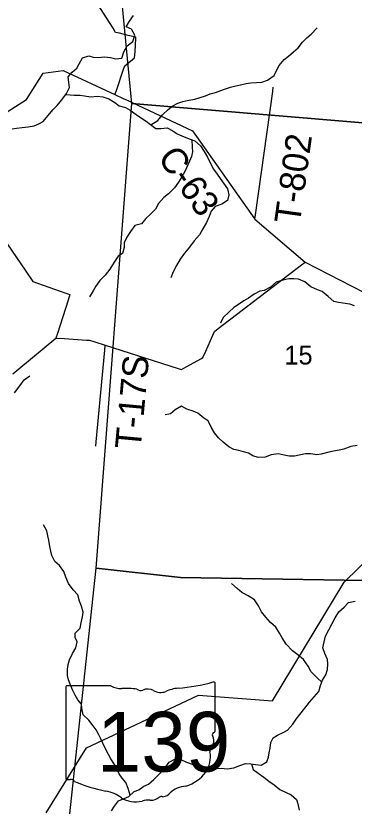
# Model space of a CAD drawing. Extents: x 1715311 to 2083412, y 146837 to 553079.
# Drawn here: x 1900643 to 1904583, y 324418 to 333622 of the extents above; entities that cross this region are included whole.
import ezdxf

# ---------------------------------------------------------------- set-up
doc = ezdxf.new("R2010")
doc.units = 0
for name, color, linetype in [('GM_X_County_Road', 7, 'Continuous'), ('GM_X_County_Road_Text', 7, 'Continuous'), ('GM_X_Minor_River', 7, 'Continuous'), ('GM_X_Section', 7, 'Continuous'), ('GM_X_Section_Text', 7, 'Continuous'), ('GM_X_State_Location', 7, 'Continuous'), ('GM_X_State_Route', 7, 'Continuous'), ('GM_X_State_Shield', 7, 'Continuous'), ('GM_X_Township_Road', 7, 'Continuous'), ('GM_X_Township_Road_Text', 7, 'Continuous'), ('GM_X_Township_ROW', 7, 'Continuous')]:
    doc.layers.add(name, color=color, linetype=linetype)

msp = doc.modelspace()

# ---------------------------------------------------------------- linework, layer by layer
at = {"layer": 'GM_X_County_Road'}
for points in [[(1895522.8, 333111.5), (1895631.1, 333150.8), (1896318.1, 332920.2), (1897109.3, 333251), (1897359.6, 333535.8), (1897940.5, 333377.3), (1899174.4, 332376.6), (1899334.6, 332039.7), (1899795.3, 331853.1), (1900055.7, 332196.1), (1900768.7, 332649.2), (1900963, 332954.1), (1901195.4, 332986.1), (1901797.2, 332704.6), (1901891.8, 332660.5)], [(1901891.8, 332660.5), (1901939.4, 332638.2)], [(1901939.4, 332638.2), (1902701.8, 332281.7), (1903427.7, 331253.6), (1904011.6, 330753.9), (1904690.6, 330402.9), (1904921, 329149.5), (1905450.8, 328846.4)]]:
    msp.add_lwpolyline(points, dxfattribs=at)
at = {"layer": 'GM_X_Minor_River'}
for points in [[(1901744.3, 333135.8), (1901808.1, 333119.5), (1901878.1, 333129.2), (1901900.3, 333201.2), (1901940.5, 333273.1), (1902004.6, 333322.9), (1902028.9, 333394.8), (1901991.2, 333465), (1901927.4, 333495.3), (1901965.6, 333561.2), (1902011.7, 333627)], [(1902216, 332353), (1902296.8, 332403.1), (1902349, 332469), (1902417.2, 332532.8), (1902469.2, 332572.6), (1902529.3, 332606.4), (1902587.3, 332624.2), (1902659.2, 332637.9), (1902727.2, 332651.6), (1902789.2, 332669.4), (1902851.2, 332691.2), (1902907.2, 332713), (1902969.2, 332730.8), (1903029.2, 332750.5), (1903085.2, 332770.3), (1903143.2, 332790.1), (1903205.2, 332805.9), (1903259.1, 332817.7), (1903323.1, 332833.5), (1903381.1, 332843.3), (1903447, 332845), (1903506.9, 332848.8), (1903574.9, 332872.5), (1903649, 332928.3), (1903683.2, 332992.2), (1903709.4, 333044.1), (1903767.6, 333114), (1903817.7, 333153.8), (1903875.8, 333201.6), (1903931.9, 333247.4), (1903980.1, 333313.3), (1904032.2, 333367.1), (1904082.3, 333409), (1904152.4, 333482.7)], [(1900598.7, 332305.6), (1900652.6, 332313.4), (1900716.6, 332321.1), (1900786.5, 332328.9), (1900856.5, 332342.6), (1900910.5, 332362.4), (1900962.5, 332392.2), (1901018.7, 332462.1), (1901074.9, 332525.9), (1901125, 332577.8), (1901177.2, 332643.6), (1901233.4, 332715.4), (1901269.6, 332787.3), (1901261.8, 332843.4), (1901252.1, 332909.5), (1901300.2, 332967.3), (1901352.3, 333011.2), (1901380.5, 333063.1), (1901420.7, 333131), (1901492.7, 333156.7), (1901544.5, 333138.5), (1901604.5, 333138.3), (1901674.4, 333146), (1901744.3, 333135.8)], [(1901227.2, 332707.5), (1901321.2, 332699.1), (1901391.1, 332696.8), (1901443, 332688.6), (1901516.9, 332678.3), (1901590.8, 332686), (1901656.7, 332677.8), (1901724.5, 332653.5), (1901796.3, 332611.2), (1901848.1, 332575), (1901919.9, 332552.7), (1901973.7, 332524.5), (1902043.4, 332472.1), (1902095.2, 332435.9), (1902159, 332395.7), (1902212.8, 332355.4), (1902274.5, 332309.1), (1902332.5, 332310.9), (1902404.4, 332316.7), (1902470.2, 332284.4), (1902522, 332248.2), (1902601.7, 332211.8), (1902673.6, 332185.5), (1902725.4, 332165.3), (1902795.1, 332109), (1902836.8, 332040.8), (1902874.5, 331976.6), (1902906.2, 331910.5), (1902945.9, 331836.2), (1902987.6, 331776), (1903023.4, 331725.9), (1903061.2, 331673.7), (1903106.9, 331607.5), (1903124.6, 331537.4), (1903108.3, 331469.4), (1903040.3, 331427.6), (1902964.3, 331399.9), (1902916.1, 331346), (1902893.9, 331284.1), (1902861.7, 331214.1), (1902821.5, 331142.2), (1902783.3, 331072.3), (1902719.1, 331000.5), (1902666.9, 330926.7), (1902608.7, 330858.9), (1902556.5, 330787), (1902512.3, 330713.1), (1902476.1, 330641.2), (1902445.9, 330571.3)], [(1902690.7, 332178.9), (1902695.2, 332091.4), (1902701, 332039.3), (1902686.8, 331985.3), (1902666.6, 331929.4), (1902630.4, 331853.5), (1902608.2, 331799.5), (1902576, 331745.6), (1902535.9, 331685.7), (1902489.7, 331617.9), (1902419.5, 331550.1), (1902365.4, 331506.3), (1902305.2, 331434.4), (1902271.1, 331370.5), (1902208.9, 331306.7), (1902156.8, 331260.9), (1902104.6, 331199), (1902026.7, 331179.3), (1901978.5, 331111.5), (1901934.3, 331043.6), (1901906.1, 330979.6), (1901903.9, 330925.6), (1901885.6, 330855.6), (1901833.6, 330821.8), (1901789.4, 330751.9), (1901737.1, 330670.1), (1901685, 330602.2), (1901620.8, 330540.4), (1901574.6, 330472.6), (1901542.5, 330420.7), (1901502.3, 330350.8)], [(1904585.9, 330244.8), (1904530.1, 330265.1), (1904452.2, 330277.4), (1904398.3, 330281.6), (1904346.4, 330293.8), (1904280.7, 330354.1), (1904209, 330410.4), (1904155.2, 330432.6), (1904079.4, 330464.9), (1904007.7, 330525.2), (1903933.9, 330553.6), (1903880, 330559.8), (1903822.1, 330558), (1903750.1, 330544.3), (1903676.1, 330520.5), (1903608, 330460.8), (1903535.9, 330425), (1903484, 330415.2), (1903417.9, 330381.4), (1903351.8, 330335.6), (1903295.8, 330303.8), (1903245.7, 330266), (1903179.7, 330226.2), (1903121.5, 330170.4), (1903057.4, 330108.6), (1903025.2, 330042.7)], [(1900627.3, 329233.3), (1900691.5, 329313.2), (1900739.7, 329381), (1900807.8, 329430.8)], [(1904615.9, 328619.6), (1904543.9, 328605.8), (1904463.9, 328576.1), (1904405.9, 328564.3), (1904342, 328552.6), (1904288, 328538.8), (1904200, 328519.1), (1904148.1, 328509.3), (1904078.2, 328519.6), (1904014.3, 328519.8), (1903886.3, 328492.3), (1903824.4, 328494.5), (1903766.5, 328506.8), (1903696.7, 328521), (1903616.8, 328509.3), (1903544.7, 328483.6), (1903464.8, 328477.9), (1903403, 328498.2), (1903351.2, 328528.4), (1903293.3, 328542.6), (1903239.4, 328560.8), (1903179.5, 328573.1), (1903123.7, 328601.3), (1903056, 328657.6), (1903002.3, 328707.8), (1902956.5, 328764.1), (1902916.8, 328830.3), (1902883.2, 328906.4), (1902831.3, 328936.7), (1902763.6, 328995), (1902707.8, 329019.2), (1902636, 329039.5), (1902572.2, 329075.8), (1902498.1, 329032), (1902444, 328988.2), (1902380.1, 328974.4)], [(1901976.2, 324544.9), (1901952.5, 324625), (1901924.8, 324695.1), (1901881.1, 324745.3), (1901845.3, 324795.5), (1901817.5, 324851.7), (1901791.8, 324901.8), (1901748.1, 324968), (1901720.3, 325018.1), (1901688.6, 325084.3), (1901654.8, 325150.5), (1901631.1, 325200.6), (1901607.3, 325254.8), (1901579.5, 325306.9), (1901531.8, 325371.1), (1901494.1, 325421.3), (1901426.4, 325483.6), (1901410.7, 325557.7), (1901408.9, 325607.8), (1901365.1, 325658), (1901335.3, 325710.1), (1901303.6, 325774.3), (1901273.9, 325840.5), (1901256.1, 325890.5), (1901244.3, 325940.6), (1901244.6, 326012.7), (1901250.7, 326066.7), (1901266.9, 326122.7), (1901303.2, 326196.6), (1901343.3, 326260.5), (1901355.6, 326330.5), (1901333.8, 326380.6), (1901332, 326434.6), (1901392.1, 326492.5), (1901404.4, 326554.5), (1901418.6, 326624.5), (1901428.8, 326678.5), (1901409.1, 326748.6), (1901383.3, 326804.7), (1901363.6, 326878.8), (1901309.9, 326939.1), (1901258.2, 327009.3), (1901226.5, 327083.5), (1901200.8, 327149.7), (1901151.1, 327221.9), (1901097.4, 327268.1), (1901063.7, 327336.3), (1901051.9, 327388.4), (1901038.1, 327442.5), (1901026.4, 327516.6), (1901016.6, 327566.7), (1901004.8, 327622.8), (1900965.1, 327693)], [(1904205.4, 325863.2), (1904152.5, 325913.4), (1904082.8, 325981.8), (1904045.1, 326050), (1903991.4, 326124.2), (1903927.7, 326180.5), (1903864, 326228.8), (1903792.4, 326303.1), (1903744.7, 326377.3), (1903713, 326433.5), (1903669.3, 326503.7), (1903609.5, 326556), (1903555.8, 326620.2), (1903502.1, 326682.5), (1903468.4, 326750.7), (1903422.8, 326820.9), (1903347, 326869.2), (1903273.3, 326907.5), (1903221.5, 326951.8), (1903155.8, 327010)], [(1904117.7, 325691.4), (1904169.8, 325753.3), (1904190.1, 325825.2), (1904214.3, 325885.2), (1904252.5, 325949.1), (1904270.7, 326011.1), (1904276.9, 326075.1), (1904271.1, 326125.1), (1904239.4, 326197.3), (1904217.7, 326261.4), (1904231.9, 326331.4), (1904248.1, 326397.4), (1904286.4, 326471.3), (1904326.6, 326545.2), (1904360.8, 326613.1), (1904405, 326681), (1904465.1, 326736.8), (1904515.2, 326790.7), (1904593.2, 326804.4)], [(1901757.8, 324365.5), (1901790, 324419.5), (1901838.1, 324481.3), (1901906.1, 324507.1), (1901960.2, 324528.9), (1902022.3, 324590.7), (1902076.3, 324606.5), (1902134.4, 324650.3), (1902186.4, 324676.1), (1902250.5, 324729.9), (1902312.7, 324789.7), (1902378.8, 324861.5), (1902429, 324931.4), (1902493.1, 324967.1), (1902565, 324962.9), (1902630.8, 324930.6), (1902706.6, 324902.3), (1902768.4, 324890), (1902828.3, 324877.8), (1902902.2, 324859.5), (1902960.1, 324857.3), (1903034, 324859), (1903101.9, 324854.7), (1903179.8, 324864.4), (1903249.8, 324892.2), (1903315.8, 324914), (1903379.7, 324911.7), (1903431.7, 324903.5), (1903499.5, 324895.2), (1903563.6, 324933), (1903585.8, 324987), (1903591.9, 325039), (1903604.1, 325095), (1903612.4, 325161), (1903640.5, 325212.9), (1903690.6, 325246.7), (1903756.6, 325276.5), (1903806.6, 325304.3), (1903868.8, 325374.1), (1903909, 325430), (1903951.1, 325483.9), (1904007.3, 325557.7), (1904063.5, 325627.6), (1904117.7, 325691.4)], [(1903388.9, 324910.2), (1903405.5, 324845.5), (1903463.2, 324801.3), (1903531, 324757), (1903588.7, 324710.8), (1903650.5, 324666.5), (1903718.2, 324612.2), (1903792, 324575.9), (1903849.8, 324551.6), (1903911.5, 324495.3), (1903925.3, 324445.3), (1903941, 324373.2)]]:
    msp.add_lwpolyline(points, dxfattribs=at)
at = {"layer": 'GM_X_Section'}
for points in [[(1901907.9, 338140.1), (1906715.7, 337800.2), (1906304.2, 332238.5), (1901992.5, 332601.4), (1901718.4, 335466.2)], [(1906304.2, 332238.5), (1905895.5, 327024.8), (1902559.2, 327081.7), (1901579.3, 327187.8), (1901992.5, 332601.4)], [(1901579.3, 327187.8), (1902559.2, 327081.7), (1905895.5, 327024.8), (1905532, 321487), (1901000.1, 321792.4)]]:
    msp.add_lwpolyline(points, close=True, dxfattribs=at)
at = {"layer": 'GM_X_State_Route'}
msp.add_lwpolyline([(1900996.1, 324342.1), (1901467.7, 325099), (1902232.4, 325458.1), (1902768.2, 325709.8), (1903633.1, 325645.7), (1904466.1, 327027.8), (1904801.7, 327356.2)], dxfattribs=at)
at = {"layer": 'GM_X_State_Shield'}
for p, q in [((1902964.2, 325294), (1902964.2, 325846.7)), ((1901224, 325802.3), (1901224, 324745.7)), ((1901750.7, 325820.5), (1901241.1, 325820.5)), ((1902964, 325294.1), (1902964.2, 325294))]:
    msp.add_line(p, q, dxfattribs=at)
for centre, major_axis, start_param, end_param in [((1902344.3, 327261.1), (1845.5, 0), 4.814394, 5.042369), ((1902944.9, 325849), (19.4, 0), 6.141152, 7.989035), ((1901243.9, 325804.6), (20.2, 0), 1.712693, 3.28349), ((1901872.1, 325943.2), (195.5, 0), 4.042523, 4.731795), ((1901936.9, 325227.3), (702, 0), 1.404758, 1.657858), ((1902096.3, 325810.1), (56.4, 0), 3.836095, 5.185415), ((1902179.1, 325687.9), (117.3, 0), 0.950623, 2.079405), ((1902330.5, 325855.4), (141.1, 0), 4.081561, 5.145723), ((1902579.7, 325497.8), (371.3, 0), 1.699011, 2.107814), ((1902959.7, 325253.4), (30, 0), 1.883978, 3.671073), ((1902943.5, 325291.8), (20.7, 0), 5.05454, 6.418171), ((1902769, 325183.5), (180, 0), 5.934695, 6.695948), ((1903033.6, 325062.6), (130.9, 0), 2.387724, 3.262537), ((1902447.7, 324992.3), (461.6, 0), 5.101752, 6.440018), ((1901244.1, 324743.4), (20.3, 0), 3.00124, 4.508301), ((1901247.2, 324851.5), (155.2, 0), 4.665946, 4.897461), ((1901278.9, 324684.7), (56, 0), 0.519207, 1.627899), ((1901985.5, 325634.1), (1332.7, 0), 4.195997, 4.488961), ((1902642.3, 324449.1), (252.8, 0), 1.647645, 2.488434), ((1901588.2, 324271), (417, 0), 0.823519, 1.323587), ((1902322, 324643.3), (149.1, 0), 4.937069, 5.64225), ((1902039.2, 324679.5), (264.6, 0), 4.026481, 4.996735), ((1902192.1, 324314.2), (217.4, 0), 1.495662, 1.94098), ((1902211.4, 324600.4), (141, 0), 4.691044, 5.507374), ((1902338.9, 324498), (39.7, 0), 1.147584, 2.315152)]:
    msp.add_ellipse(centre, major_axis=major_axis, ratio=0.8, start_param=start_param, end_param=end_param, dxfattribs=at)
at = {"layer": 'GM_X_Township_Road'}
for points in [[(1901797.2, 332704.6), (1901814, 332754), (1901897.7, 333000.7), (1901910.4, 333038.2), (1901960.6, 333078.9), (1902001, 333111.7), (1902026.6, 333132.5), (1902030.7, 333203.6), (1902039.9, 333359.7), (1902040.7, 333373.1), (1901952.4, 333394.1), (1901851, 333418.2), (1901804.3, 333429.3), (1901774.4, 333476.8), (1901524.8, 333873.8)], [(1903427.7, 331253.6), (1903434.8, 331304.8), (1903634.2, 332740.2), (1903641, 332791.5)], [(1900606.5, 329454.6), (1900676.3, 329511.9), (1901109, 329867.8), (1901209.9, 329863.1), (1901464, 329846), (1901499.8, 329843.6), (1901562.7, 329823.6), (1901684.8, 329784.7), (1902533.4, 329514.9), (1902571.5, 329502.6), (1902625.4, 329532.8), (1902803.1, 329632.5), (1902821.8, 329643), (1902854.4, 329716.5), (1902936.9, 329902.8), (1902956, 329945.8), (1902999.5, 329979.1), (1903970, 330722.1), (1904011.6, 330753.9)], [(1900751.2, 330658.1), (1900840.9, 330527.5), (1900895.7, 330508), (1901224.9, 330391.6), (1901271.5, 330375.1), (1901251.1, 330311.2), (1901126.8, 329923.3), (1901109, 329867.8)], [(1901574, 328610.2), (1901578.7, 328661), (1901679.3, 329726.6), (1901684.8, 329784.7)]]:
    msp.add_lwpolyline(points, dxfattribs=at)
at = {"layer": 'GM_X_Township_ROW'}
msp.add_lwpolyline([(1900178.2, 331493.4), (1900751.2, 330658.1)], dxfattribs=at)

# ---------------------------------------------------------------- texts
at = {"layer": 'GM_X_County_Road_Text'}
msp.add_text('C-63', height=300, rotation=305.21747, dxfattribs=at).set_placement((1902285.7, 331970.1))
at = {"layer": 'GM_X_Section_Text'}
msp.add_text('15', height=221, rotation=0.00001, dxfattribs=at).set_placement((1903769.7, 329561.2))
at = {"layer": 'GM_X_State_Location'}
for s in ['s', 'r']:
    msp.add_text(s, height=1, dxfattribs=at).set_placement((1902074.5, 325203.8))
msp.add_text('139', height=1, rotation=0.00001, dxfattribs=at).set_placement((1901721.5, 325131))
at = {"layer": 'GM_X_State_Shield'}
msp.add_text('139', height=696.1, dxfattribs=at).set_placement((1901586.6, 324820.2))
at = {"layer": 'GM_X_Township_Road_Text'}
for s, rotation, p in [('T-802', 82.10831, (1903948.9, 331187.2)), ('T-17S', 84.75539, (1902095.4, 328566.7))]:
    msp.add_text(s, height=300, rotation=rotation, dxfattribs=at).set_placement(p)

doc.saveas('drawing.dxf')
